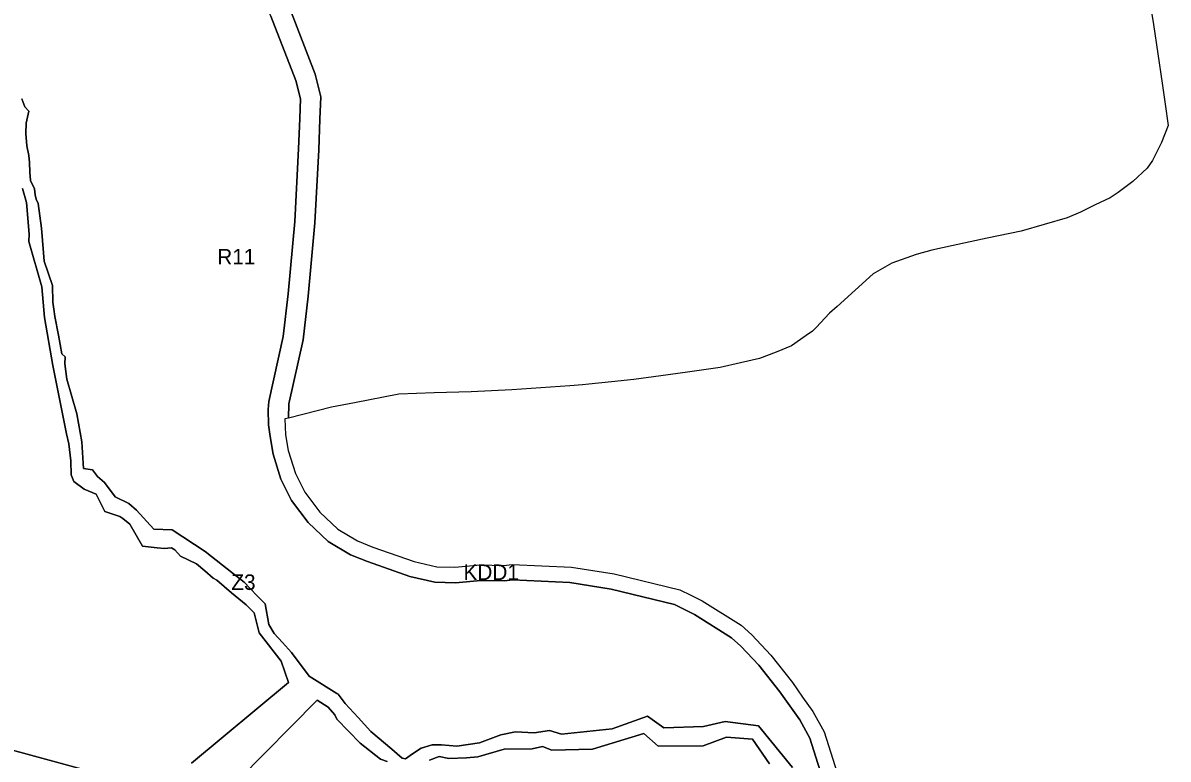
# Model space of a CAD drawing. Extents: x 7440055 to 7442242, y 5549003 to 5552256.
# Drawn here: x 7441503 to 7442240, y 5550092 to 5550566 of the extents above; entities that cross this region are included whole.
import ezdxf

# ---------------------------------------------------------------- set-up
doc = ezdxf.new("R2010")
doc.units = 0
doc.layers.add('linie_rozgraniczajace', color=7, linetype='Continuous')
doc.layers.add('oznaczenia_przeznaczen', color=7, linetype='Continuous')

msp = doc.modelspace()

# ---------------------------------------------------------------- linework, layer by layer
at = {"layer": 'linie_rozgraniczajace'}
for points in [[(7441699.94, 5550232.15), (7441687.08, 5550244.43), (7441676.3, 5550258.66), (7441669.51, 5550272.27), (7441664.38, 5550288.43), (7441662.51, 5550299.83), (7441661.39, 5550307.27), (7441661.19, 5550317.23), (7441661.63, 5550322.42), (7441670.89, 5550364.3), (7441674.11, 5550391.57), (7441678.34, 5550438.21), (7441680.84, 5550485.01), (7441681.55, 5550504.54), (7441682.13, 5550517.19), (7441679.16, 5550529.05), (7441663.07, 5550570.43), (7441616.45, 5550684.43), (7441609.63, 5550699.87), (7441597.33, 5550732.36), (7441584.17, 5550767.08), (7441578.94, 5550780.47), (7441572.79, 5550794.83), (7441569.04, 5550806.07)], [(7441675.15, 5550575.24), (7441691.57, 5550533), (7441695.2, 5550518.5), (7441694.54, 5550504), (7441693.82, 5550484.42), (7441691.31, 5550437.28), (7441687.04, 5550390.22), (7441683.72, 5550362.12), (7441674.51, 5550320.8), (7441674.32, 5550311.7), (7441672.08, 5550311.13), (7441672.47, 5550300.84), (7441674.13, 5550290.77), (7441678.81, 5550276.03), (7441684.83, 5550263.96), (7441694.57, 5550251.11), (7441706.01, 5550240.18), (7441718.68, 5550232.73), (7441728.68, 5550228.65), (7441755.18, 5550219.3), (7441769.75, 5550215.97), (7441781.43, 5550215.66), (7441797.8, 5550217.19), (7441812.73, 5550216.82), (7441818.19, 5550217.51), (7441856.36, 5550215.7), (7441883.92, 5550211.42), (7441926.19, 5550201.18), (7441933.18, 5550197.68), (7441940.43, 5550194.05), (7441965.56, 5550178.29), (7441972.41, 5550172.08), (7441984.61, 5550159.08), (7441998.56, 5550141.43), (7442005.16, 5550132.1), (7442011.76, 5550122.77), (7442019.12, 5550109.63), (7442030.16, 5550074.49)], [(7442228.82, 5550578.31), (7442230.98, 5550565.09), (7442233.7, 5550546.23), (7442236.42, 5550527.37), (7442238.4, 5550513.71), (7442240.34, 5550499.96), (7442236.09, 5550489.04), (7442230.3, 5550477.49), (7442226.84, 5550472.6), (7442217.62, 5550463.99), (7442208.13, 5550456.8), (7442207.67, 5550456.45), (7442202.98, 5550453.49), (7442193.5, 5550448.9), (7442184.02, 5550444.31), (7442175.42, 5550440.52), (7442145.76, 5550432.03), (7442123.9, 5550427.4), (7442102.04, 5550422.76), (7442088.36, 5550419.77), (7442078.28, 5550417.04), (7442062.48, 5550411.31), (7442050.52, 5550404.43), (7442038.98, 5550393.96), (7442027.43, 5550383.49), (7442022.49, 5550379.3), (7442013.84, 5550370.09), (7442011.44, 5550367.53), (7442007.5, 5550364.79), (7441998.03, 5550358.22), (7441988.07, 5550354.11), (7441977.43, 5550350.07), (7441965.12, 5550347.16), (7441952.02, 5550344.34), (7441931.07, 5550341.15), (7441913.86, 5550338.85), (7441896.65, 5550336.55), (7441882.13, 5550335), (7441867.62, 5550333.45), (7441863.49, 5550333.02), (7441855.28, 5550332.51), (7441836.63, 5550331.14), (7441817.98, 5550329.78), (7441804.95, 5550329.14), (7441791.92, 5550328.51), (7441768, 5550327.9), (7441745.24, 5550326.97), (7441716.75, 5550321.59), (7441701.96, 5550318.78), (7441674.32, 5550311.7)], [(7441674.32, 5550311.7), (7441674.51, 5550320.8), (7441683.72, 5550362.12), (7441687.04, 5550390.22), (7441691.31, 5550437.28), (7441693.82, 5550484.42), (7441694.54, 5550504), (7441695.2, 5550518.5), (7441691.57, 5550533), (7441675.15, 5550575.24)], [(7441663.07, 5550570.43), (7441679.16, 5550529.05), (7441682.13, 5550517.19), (7441681.55, 5550504.54), (7441680.84, 5550485.01), (7441678.34, 5550438.21), (7441674.11, 5550391.57), (7441670.89, 5550364.3), (7441661.63, 5550322.42), (7441661.19, 5550317.23), (7441661.39, 5550307.27), (7441662.51, 5550299.83), (7441664.38, 5550288.43), (7441669.51, 5550272.27), (7441676.3, 5550258.66), (7441687.08, 5550244.43), (7441699.94, 5550232.15), (7441714.24, 5550223.74), (7441725.13, 5550219.3), (7441752.39, 5550209.68), (7441768.49, 5550206), (7441781.76, 5550205.65), (7441798.14, 5550207.18), (7441813.24, 5550206.81), (7441818.59, 5550207.48), (7441855.36, 5550205.74), (7441881.97, 5550201.61), (7441922.73, 5550191.73), (7441935.53, 5550185.33), (7441959.5, 5550170.29), (7441965.39, 5550164.95), (7441977.03, 5550152.55), (7441990.55, 5550135.44), (7442003.3, 5550117.43), (7442009.89, 5550105.65), (7442020.35, 5550072.34)], [(7441502.65, 5550517.13), (7441504.74, 5550512.02), (7441507.17, 5550509.24), (7441505.61, 5550501.52), (7441505.34, 5550494.87), (7441506.05, 5550486.94), (7441507.3, 5550480.76), (7441507.72, 5550476.16), (7441507.9, 5550469.98), (7441508.41, 5550464.58), (7441510.92, 5550459.17), (7441511.23, 5550455.42), (7441512.03, 5550452.66), (7441513.34, 5550449.8), (7441515.38, 5550433.94), (7441516.73, 5550418.1), (7441517.09, 5550412.6), (7441522.48, 5550397.05), (7441522.71, 5550386.39), (7441523.38, 5550381.69), (7441524.05, 5550376.99), (7441526.31, 5550364.96), (7441528.57, 5550352.93), (7441530.72, 5550351.21), (7441530.33, 5550346.5), (7441531.61, 5550336.79), (7441534.92, 5550325.57), (7441538.22, 5550314.35), (7441541.44, 5550296.3), (7441542.37, 5550279.29), (7441548.26, 5550278.37), (7441551.39, 5550274.03), (7441555.89, 5550270.21), (7441562.87, 5550261), (7441571.6, 5550256.74), (7441576.54, 5550252.38), (7441587.77, 5550240.09), (7441599.55, 5550239.68), (7441620.79, 5550225.76), (7441638.88, 5550211.38), (7441645.73, 5550206.04), (7441653.98, 5550197.38), (7441659.25, 5550192.02), (7441661.62, 5550178.7), (7441665.06, 5550173.04), (7441670.39, 5550167.22), (7441676.24, 5550160.8), (7441687.61, 5550145.63), (7441705.42, 5550134.46), (7441706.4, 5550133.93), (7441710.9, 5550127.9), (7441719.13, 5550118.88), (7441727.36, 5550109.86), (7441740.9, 5550098.53), (7441744.28, 5550095.49), (7441747.46, 5550092.81), (7441749.66, 5550092.44), (7441754.24, 5550095.56), (7441759.68, 5550099.28), (7441766.81, 5550101.36), (7441772.82, 5550101.4), (7441782.64, 5550100.58), (7441797.34, 5550102.6), (7441810.99, 5550107.86), (7441820.41, 5550109.67), (7441832.53, 5550109.16), (7441842.21, 5550110.64), (7441849.96, 5550108.18), (7441882.58, 5550111.69), (7441905.43, 5550119.84)], [(7441719.13, 5550118.88), (7441710.9, 5550127.9), (7441706.4, 5550133.93), (7441705.42, 5550134.46), (7441687.61, 5550145.63), (7441676.24, 5550160.8), (7441670.39, 5550167.22), (7441665.06, 5550173.04), (7441661.62, 5550178.7), (7441659.25, 5550192.02), (7441653.98, 5550197.38), (7441645.73, 5550206.04), (7441638.88, 5550211.38), (7441620.79, 5550225.76), (7441599.55, 5550239.68), (7441587.77, 5550240.09), (7441576.54, 5550252.38), (7441571.6, 5550256.74), (7441562.87, 5550261), (7441555.89, 5550270.21), (7441551.39, 5550274.03), (7441548.26, 5550278.37), (7441542.37, 5550279.29), (7441541.44, 5550296.3), (7441538.22, 5550314.35), (7441534.92, 5550325.57), (7441531.61, 5550336.79), (7441530.33, 5550346.5), (7441530.72, 5550351.21), (7441528.57, 5550352.93), (7441526.31, 5550364.96), (7441524.05, 5550376.99), (7441523.38, 5550381.69), (7441522.71, 5550386.39), (7441522.48, 5550397.05), (7441517.09, 5550412.6), (7441516.73, 5550418.1), (7441515.38, 5550433.94), (7441513.34, 5550449.8), (7441512.03, 5550452.66), (7441511.23, 5550455.42), (7441510.92, 5550459.17), (7441508.41, 5550464.58), (7441507.9, 5550469.98), (7441507.72, 5550476.16), (7441507.3, 5550480.76), (7441506.05, 5550486.94), (7441505.34, 5550494.87), (7441505.61, 5550501.52), (7441507.17, 5550509.24), (7441504.74, 5550512.02), (7441502.65, 5550517.13)], [(7441611.9, 5550089.62), (7441674.24, 5550141.39), (7441669.72, 5550155.19), (7441655.49, 5550173.4), (7441652.36, 5550186.22), (7441647.08, 5550191.45), (7441637.77, 5550199.19), (7441628.31, 5550207.38), (7441625.92, 5550208.6), (7441620.58, 5550213.27), (7441615.24, 5550217.93), (7441604.78, 5550222.83), (7441601.14, 5550226.86), (7441599.04, 5550228.24), (7441594.43, 5550227.77), (7441589.83, 5550228.13), (7441580.31, 5550229.32), (7441572.31, 5550243.44), (7441567.83, 5550247.06), (7441565.76, 5550248.38), (7441556.23, 5550251.5), (7441550.59, 5550262.63), (7441542.93, 5550265.85), (7441536.26, 5550270.84), (7441534.59, 5550275.17), (7441534.3, 5550284.22), (7441532.93, 5550295.16), (7441531.46, 5550301.6), (7441527.97, 5550318.64), (7441522.7, 5550345.48), (7441517.26, 5550376.44), (7441515.65, 5550396.14), (7441507.18, 5550425.34), (7441507.5, 5550430.12), (7441505.73, 5550450.53), (7441504.45, 5550455.02), (7441503.17, 5550459.51)], [(7441503.17, 5550459.51), (7441504.45, 5550455.02), (7441505.73, 5550450.53), (7441507.5, 5550430.12), (7441507.18, 5550425.34), (7441515.65, 5550396.14), (7441517.26, 5550376.44), (7441522.7, 5550345.48), (7441527.97, 5550318.64), (7441531.46, 5550301.6), (7441532.93, 5550295.16), (7441534.3, 5550284.22), (7441534.59, 5550275.17), (7441536.26, 5550270.84), (7441542.93, 5550265.85), (7441550.59, 5550262.63), (7441556.23, 5550251.5), (7441565.76, 5550248.38), (7441567.83, 5550247.06), (7441572.31, 5550243.44), (7441580.31, 5550229.32), (7441589.83, 5550228.13), (7441594.43, 5550227.77), (7441599.04, 5550228.24), (7441601.14, 5550226.86), (7441604.78, 5550222.83), (7441615.24, 5550217.93), (7441620.58, 5550213.27), (7441625.92, 5550208.6), (7441628.31, 5550207.38), (7441637.77, 5550199.19), (7441647.08, 5550191.45), (7441652.36, 5550186.22), (7441655.49, 5550173.4), (7441669.72, 5550155.19), (7441674.24, 5550141.39), (7441611.9, 5550089.62)], [(7441559.01, 5550080.87), (7441481.52, 5550102.04), (7441458.62, 5550122.98), (7441439.11, 5550152.95), (7441420.78, 5550162.2), (7441419.64, 5550173.38), (7441419.49, 5550178.36), (7441419.62, 5550191.63), (7441420.65, 5550206.43), (7441423.8, 5550227.45), (7441428.93, 5550226.36), (7441433.58, 5550225.37), (7441436.09, 5550225.06), (7441438.59, 5550224.74), (7441441.1, 5550224.43), (7441443.61, 5550224.11), (7441448.75, 5550223.85), (7441453.9, 5550223.59), (7441458.14, 5550223.5), (7441462.39, 5550223.41), (7441466.81, 5550223.85), (7441471.23, 5550224.29), (7441471.86, 5550239.66)], [(7442020.35, 5550072.34), (7442009.89, 5550105.65), (7442003.3, 5550117.43), (7441990.55, 5550135.44), (7441977.03, 5550152.55), (7441965.39, 5550164.95), (7441959.5, 5550170.29), (7441935.53, 5550185.33), (7441922.73, 5550191.73), (7441881.97, 5550201.61), (7441855.36, 5550205.74), (7441818.59, 5550207.48), (7441813.24, 5550206.81), (7441798.14, 5550207.18), (7441781.76, 5550205.65), (7441768.49, 5550206), (7441752.39, 5550209.68), (7441725.13, 5550219.3), (7441714.24, 5550223.74), (7441699.94, 5550232.15)], [(7441477.25, 5550088.28), (7441463.14, 5550097.77), (7441436.93, 5550126.14), (7441434.29, 5550130.17), (7441431.64, 5550134.2), (7441428.2, 5550140.03), (7441426.07, 5550145.2), (7441423.93, 5550150.36), (7441420.78, 5550162.2), (7441439.11, 5550152.95), (7441458.62, 5550122.98), (7441481.52, 5550102.04), (7441559.01, 5550080.87)], [(7441737.76, 5550090.54), (7441733.44, 5550092.16), (7441720.4, 5550102.47), (7441705.5, 5550117.87), (7441704.17, 5550120.72), (7441699.94, 5550125.5), (7441692.73, 5550130), (7441642.28, 5550079.02)], [(7441642.28, 5550079.02), (7441692.73, 5550130), (7441699.94, 5550125.5), (7441704.17, 5550120.72), (7441705.5, 5550117.87), (7441720.4, 5550102.47), (7441733.44, 5550092.16), (7441737.76, 5550090.54)], [(7441998.68, 5550086.75), (7441976.67, 5550113.66), (7441955.39, 5550116.33), (7441941.32, 5550113.15), (7441915.82, 5550112.2), (7441905.43, 5550119.84), (7441882.58, 5550111.69), (7441849.96, 5550108.18), (7441842.21, 5550110.64), (7441832.53, 5550109.16), (7441820.41, 5550109.67), (7441810.99, 5550107.86), (7441797.34, 5550102.6), (7441782.64, 5550100.58), (7441772.82, 5550101.4), (7441766.81, 5550101.36), (7441759.68, 5550099.28), (7441754.24, 5550095.56), (7441749.66, 5550092.44), (7441747.46, 5550092.81), (7441744.28, 5550095.49), (7441740.9, 5550098.53), (7441727.36, 5550109.86), (7441719.13, 5550118.88)], [(7441905.43, 5550119.84), (7441915.82, 5550112.2), (7441941.32, 5550113.15), (7441955.39, 5550116.33), (7441976.67, 5550113.66), (7441998.68, 5550086.75)], [(7441983.93, 5550089.01), (7441972.94, 5550105.02), (7441956.26, 5550106.36), (7441941.19, 5550100.8), (7441912.22, 5550100.54), (7441902.98, 5550108.74), (7441870.04, 5550098.58), (7441843.86, 5550097.94), (7441837.72, 5550100.29), (7441831.05, 5550098.85), (7441813.09, 5550098.54), (7441796.15, 5550093.69), (7441788.91, 5550092.98), (7441777.54, 5550092.64), (7441771.31, 5550093.94), (7441765.12, 5550091.38)], [(7441765.12, 5550091.38), (7441771.31, 5550093.94), (7441777.54, 5550092.64), (7441788.91, 5550092.98), (7441796.15, 5550093.69), (7441813.09, 5550098.54), (7441831.05, 5550098.85), (7441837.72, 5550100.29), (7441843.86, 5550097.94), (7441870.04, 5550098.58), (7441902.98, 5550108.74), (7441912.22, 5550100.54), (7441941.19, 5550100.8), (7441956.26, 5550106.36), (7441972.94, 5550105.02), (7441983.93, 5550089.01)]]:
    msp.add_lwpolyline(points, dxfattribs=at)

# ---------------------------------------------------------------- texts
at = {"layer": 'oznaczenia_przeznaczen'}
for s, p in [('R11', (7441628.51, 5550410.54)), ('KDD1', (7441786.94, 5550207.46)), ('Z3', (7441637.54, 5550201.04))]:
    msp.add_text(s, height=10, dxfattribs=at).set_placement(p)

doc.saveas('drawing.dxf')
